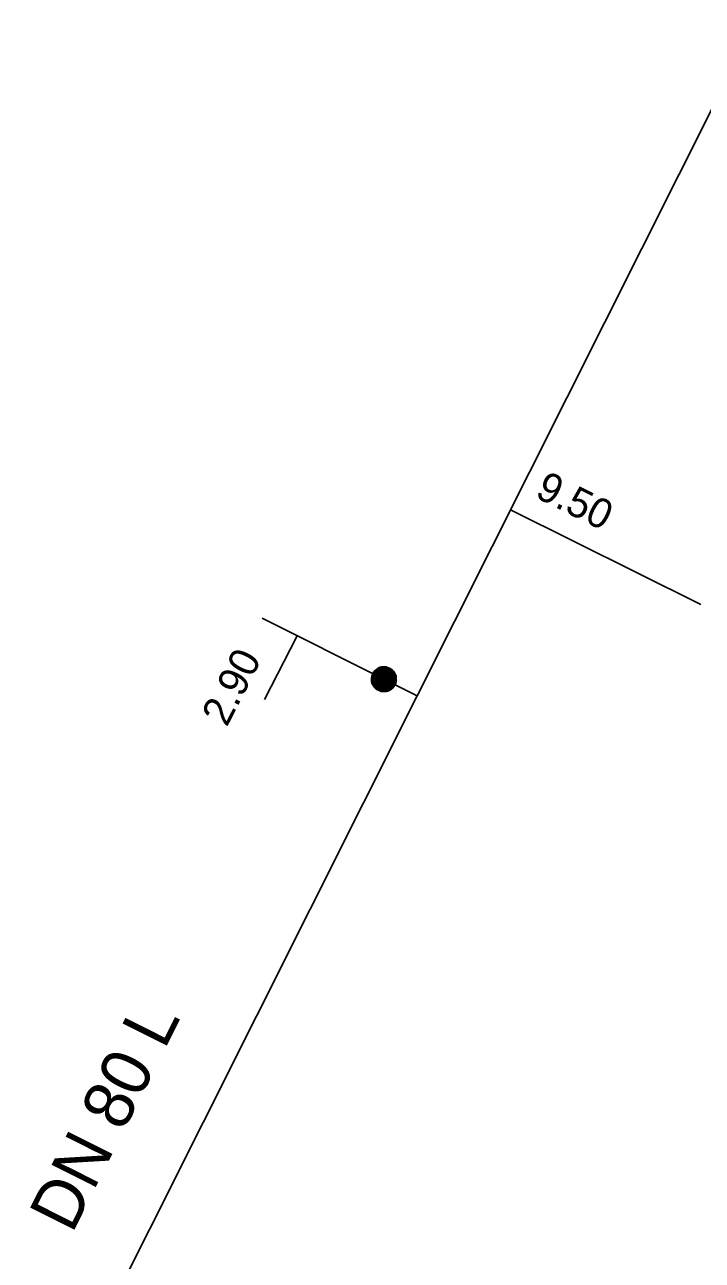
# Model space of a CAD drawing. Extents: x -820257 to -819974, y -1070894 to -1070484.
# Drawn here: x -820136.56 to -820109.19, y -1070688.11 to -1070638.2 of the extents above; entities that cross this region are included whole.
import ezdxf

# ---------------------------------------------------------------- set-up
doc = ezdxf.new("R2010")
doc.units = 0
for name, color, linetype in [('Oměrka vodovodu', 7, 'Continuous'), ('Oměrka-text', 7, 'Continuous'), ('Přípojka vodovodu', 7, 'Continuous'), ('Přípojkový uzávěr', 7, 'Continuous'), ('Roz-řad', 7, 'Continuous'), ('Roz-řad-popis základní', 7, 'Continuous')]:
    doc.layers.add(name, color=color, linetype=linetype)

msp = doc.modelspace()

# ---------------------------------------------------------------- linework, layer by layer
at = {"layer": 'Oměrka vodovodu'}
for p, q in [((-820116.938, -1070657.793), (-820109.251, -1070661.611)), ((-820126.874, -1070665.459), (-820125.552, -1070662.878))]:
    msp.add_line(p, q, dxfattribs=at)
at = {"layer": 'Přípojka vodovodu'}
msp.add_lwpolyline([(-820120.711, -1070665.309), (-820122.052, -1070664.636), (-820126.966, -1070662.168)], dxfattribs=at)
at = {"layer": 'Přípojkový uzávěr'}
for points in [[(-820121.828, -1070664.189), (-820121.715, -1070664.245), (-820121.637, -1070664.356), (-820121.559, -1070664.468), (-820121.553, -1070664.606), (-820121.546, -1070664.743), (-820121.605, -1070664.86), (-820121.663, -1070664.976), (-820121.776, -1070665.053), (-820121.888, -1070665.13), (-820122.024, -1070665.135), (-820122.16, -1070665.141), (-820122.277, -1070665.082), (-820122.392, -1070665.024), (-820122.469, -1070664.912), (-820122.546, -1070664.799), (-820122.552, -1070664.664), (-820122.557, -1070664.528), (-820122.499, -1070664.412), (-820122.44, -1070664.295), (-820122.326, -1070664.217), (-820122.212, -1070664.14), (-820122.076, -1070664.136), (-820121.941, -1070664.132), (-820121.828, -1070664.189)], [(-820121.849, -1070664.23), (-820121.951, -1070664.179), (-820122.074, -1070664.183), (-820122.197, -1070664.186), (-820122.3, -1070664.256), (-820122.404, -1070664.327), (-820122.457, -1070664.433), (-820122.51, -1070664.538), (-820122.505, -1070664.661), (-820122.5, -1070664.784), (-820122.43, -1070664.886), (-820122.36, -1070664.988), (-820122.256, -1070665.04), (-820122.15, -1070665.093), (-820122.026, -1070665.088), (-820121.903, -1070665.083), (-820121.801, -1070665.014), (-820121.7, -1070664.944), (-820121.647, -1070664.839), (-820121.594, -1070664.733), (-820121.6, -1070664.608), (-820121.606, -1070664.483), (-820121.676, -1070664.382), (-820121.747, -1070664.282), (-820121.849, -1070664.23)], [(-820121.864, -1070664.261), (-820121.77, -1070664.308), (-820121.705, -1070664.402), (-820121.639, -1070664.495), (-820121.634, -1070664.61), (-820121.628, -1070664.726), (-820121.678, -1070664.824), (-820121.726, -1070664.921), (-820121.82, -1070664.986), (-820121.914, -1070665.05), (-820122.028, -1070665.054), (-820122.142, -1070665.059), (-820122.24, -1070665.01), (-820122.337, -1070664.961), (-820122.402, -1070664.867), (-820122.466, -1070664.773), (-820122.471, -1070664.659), (-820122.475, -1070664.545), (-820122.426, -1070664.448), (-820122.377, -1070664.35), (-820122.282, -1070664.285), (-820122.186, -1070664.22), (-820122.072, -1070664.217), (-820121.958, -1070664.214), (-820121.864, -1070664.261)], [(-820121.884, -1070664.3), (-820122.024, -1070664.23), (-820122.171, -1070664.279), (-820122.317, -1070664.329), (-820122.387, -1070664.468), (-820122.457, -1070664.606), (-820122.408, -1070664.754), (-820122.359, -1070664.901), (-820122.221, -1070664.97), (-820122.081, -1070665.04), (-820121.934, -1070664.992), (-820121.787, -1070664.943), (-820121.717, -1070664.804), (-820121.647, -1070664.665), (-820121.695, -1070664.518), (-820121.743, -1070664.371), (-820121.884, -1070664.3)], [(-820121.905, -1070664.341), (-820121.782, -1070664.403), (-820121.74, -1070664.531), (-820121.698, -1070664.66), (-820121.759, -1070664.781), (-820121.82, -1070664.903), (-820121.949, -1070664.946), (-820122.078, -1070664.989), (-820122.199, -1070664.927), (-820122.322, -1070664.866), (-820122.364, -1070664.737), (-820122.407, -1070664.609), (-820122.345, -1070664.487), (-820122.284, -1070664.365), (-820122.156, -1070664.322), (-820122.027, -1070664.28), (-820121.905, -1070664.341)], [(-820121.923, -1070664.376), (-820122.03, -1070664.322), (-820122.143, -1070664.36), (-820122.256, -1070664.398), (-820122.31, -1070664.505), (-820122.364, -1070664.612), (-820122.326, -1070664.725), (-820122.289, -1070664.838), (-820122.182, -1070664.892), (-820122.075, -1070664.946), (-820121.961, -1070664.908), (-820121.848, -1070664.871), (-820121.794, -1070664.764), (-820121.741, -1070664.657), (-820121.778, -1070664.544), (-820121.815, -1070664.43), (-820121.923, -1070664.376)], [(-820121.94, -1070664.412), (-820121.846, -1070664.459), (-820121.814, -1070664.557), (-820121.782, -1070664.655), (-820121.829, -1070664.748), (-820121.875, -1070664.841), (-820121.973, -1070664.873), (-820122.071, -1070664.905), (-820122.164, -1070664.859), (-820122.256, -1070664.813), (-820122.289, -1070664.714), (-820122.322, -1070664.616), (-820122.275, -1070664.524), (-820122.229, -1070664.431), (-820122.131, -1070664.398), (-820122.033, -1070664.365), (-820121.94, -1070664.412)], [(-820121.961, -1070664.453), (-820122.036, -1070664.415), (-820122.116, -1070664.442), (-820122.196, -1070664.468), (-820122.234, -1070664.544), (-820122.271, -1070664.619), (-820122.245, -1070664.699), (-820122.219, -1070664.779), (-820122.143, -1070664.816), (-820122.068, -1070664.854), (-820121.988, -1070664.828), (-820121.908, -1070664.802), (-820121.87, -1070664.726), (-820121.833, -1070664.651), (-820121.859, -1070664.571), (-820121.885, -1070664.491), (-820121.961, -1070664.453)], [(-820121.976, -1070664.484), (-820121.914, -1070664.516), (-820121.892, -1070664.582), (-820121.87, -1070664.648), (-820121.901, -1070664.71), (-820121.933, -1070664.773), (-820121.999, -1070664.795), (-820122.065, -1070664.817), (-820122.128, -1070664.785), (-820122.19, -1070664.754), (-820122.212, -1070664.688), (-820122.234, -1070664.622), (-820122.203, -1070664.559), (-820122.171, -1070664.496), (-820122.105, -1070664.475), (-820122.039, -1070664.453), (-820121.976, -1070664.484)], [(-820121.996, -1070664.524), (-820122.042, -1070664.5), (-820122.091, -1070664.517), (-820122.14, -1070664.533), (-820122.164, -1070664.579), (-820122.187, -1070664.626), (-820122.17, -1070664.675), (-820122.154, -1070664.724), (-820122.108, -1070664.747), (-820122.062, -1070664.77), (-820122.012, -1070664.754), (-820121.963, -1070664.738), (-820121.94, -1070664.692), (-820121.917, -1070664.645), (-820121.933, -1070664.596), (-820121.949, -1070664.547), (-820121.996, -1070664.524)], [(-820122.017, -1070664.566), (-820121.988, -1070664.58), (-820121.978, -1070664.611), (-820121.968, -1070664.641), (-820121.982, -1070664.67), (-820121.997, -1070664.699), (-820122.027, -1070664.71), (-820122.058, -1070664.72), (-820122.087, -1070664.705), (-820122.116, -1070664.691), (-820122.126, -1070664.66), (-820122.137, -1070664.629), (-820122.122, -1070664.6), (-820122.107, -1070664.571), (-820122.077, -1070664.561), (-820122.046, -1070664.551), (-820122.017, -1070664.566)], [(-820122.031, -1070664.593), (-820122.049, -1070664.585), (-820122.067, -1070664.591), (-820122.085, -1070664.596), (-820122.094, -1070664.614), (-820122.103, -1070664.632), (-820122.097, -1070664.65), (-820122.091, -1070664.668), (-820122.073, -1070664.677), (-820122.055, -1070664.686), (-820122.037, -1070664.68), (-820122.019, -1070664.674), (-820122.01, -1070664.656), (-820122.001, -1070664.638), (-820122.007, -1070664.62), (-820122.013, -1070664.602), (-820122.031, -1070664.593)]]:
    msp.add_open_spline(points, degree=3, dxfattribs=at)
at = {"layer": 'Roz-řad'}
msp.add_lwpolyline([(-820107.099, -1070638.195), (-820120.711, -1070665.309), (-820144.508, -1070712.712)], dxfattribs=at)

# ---------------------------------------------------------------- texts
at = {"layer": 'Oměrka-text'}
for s, rotation, p in [(' 9.50', 333.5872, (-820116.395, -1070657.063)), (' 2.90', 62.8783, (-820128.603, -1070666.992))]:
    msp.add_text(s, height=1.2, rotation=rotation, dxfattribs=at).set_placement(p)
at = {"layer": 'Roz-řad-popis základní'}
msp.add_text('DN 80 L', height=2, rotation=63.3424, dxfattribs=at).set_placement((-820134.656, -1070687.07))

doc.saveas('drawing.dxf')
